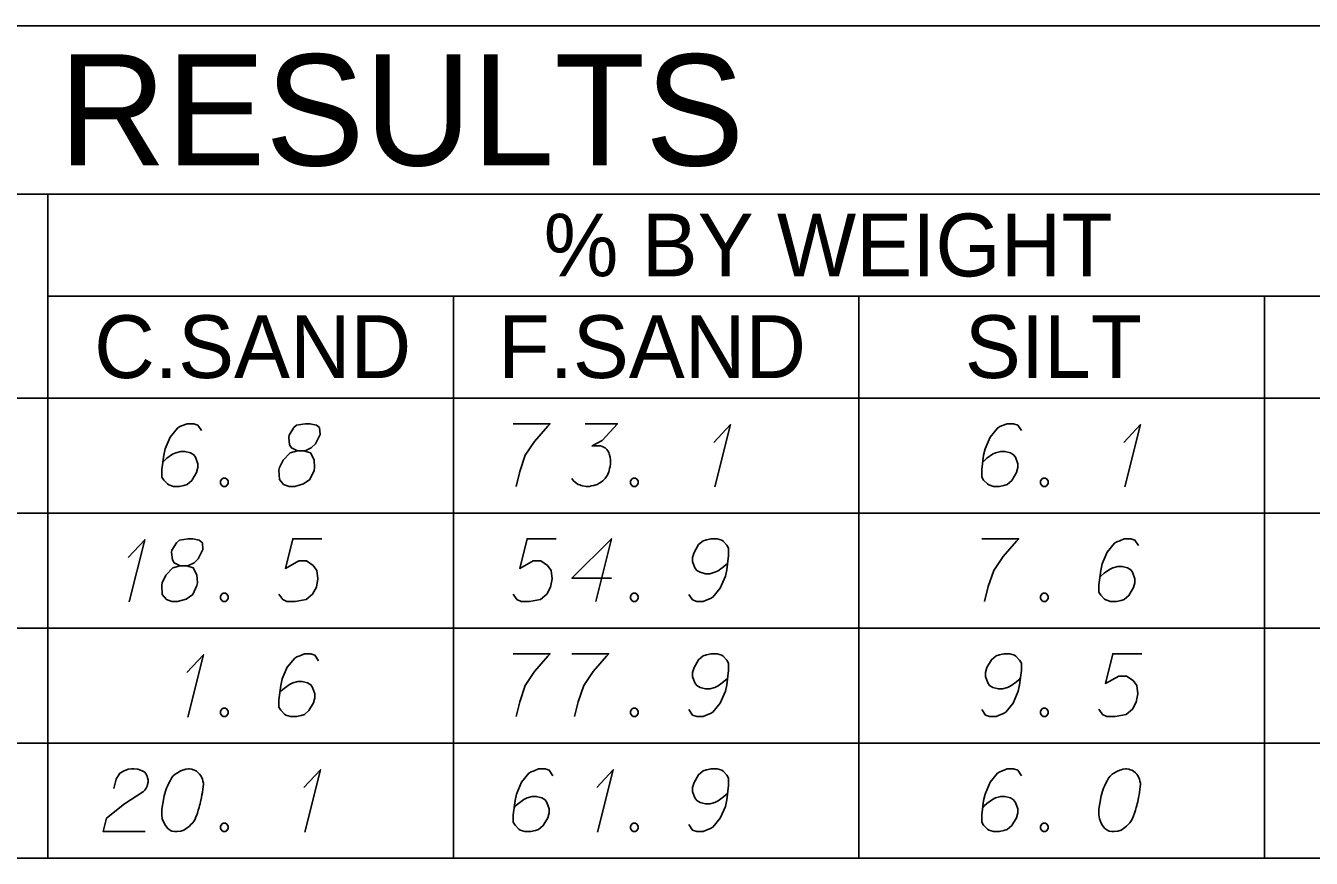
# Model space of a CAD drawing. Extents: x 2074207 to 2076812, y 516372 to 523312.
# Drawn here: x 2076524.4 to 2076622.7, y 516953.6 to 517017.2 of the extents above; entities that cross this region are included whole.
import ezdxf

# ---------------------------------------------------------------- set-up
doc = ezdxf.new("R2010")
doc.units = 0
for name, color, linetype in [('Prop DirtTable_ Soil Test Results - Outline (Major)', 7, 'Continuous'), ('Prop DirtTable_ Soil Test Results - Outline (Minor)', 7, 'Continuous'), ('Prop DirtTable_ Soil Test Results - Tx (Header - Large)', 7, 'Continuous'), ('Prop DirtTable_ Soil Test Results - Tx (Header - Small)', 7, 'Continuous'), ('Prop DirtTable_ Soil Test Results - Tx (Sample Data)', 7, 'Continuous')]:
    doc.layers.add(name, color=color, linetype=linetype)

msp = doc.modelspace()

# ---------------------------------------------------------------- linework, layer by layer
at = {"layer": 'Prop DirtTable_ Soil Test Results - Outline (Major)'}
for p, q in [((2076260.609, 517017.246), (2076811.903, 517017.246)), ((2076260.609, 516988.761), (2076811.903, 516988.761)), ((2076260.609, 516988.761), (2076811.903, 516988.761)), ((2076260.609, 516953.561), (2076811.903, 516953.561))]:
    msp.add_line(p, q, dxfattribs=at)
at = {"layer": 'Prop DirtTable_ Soil Test Results - Outline (Minor)'}
for p, q in [((2076260.609, 517004.361), (2076811.903, 517004.361)), ((2076526.074, 517004.361), (2076526.074, 516979.961)), ((2076526.074, 516996.561), (2076731.93, 516996.561)), ((2076557.094, 516996.561), (2076557.094, 516979.961)), ((2076588.114, 516996.561), (2076588.114, 516979.961)), ((2076619.134, 516979.961), (2076619.134, 516996.561)), ((2076260.609, 516979.961), (2076811.903, 516979.961)), ((2076260.609, 516979.961), (2076811.903, 516979.961)), ((2076526.074, 516979.961), (2076526.074, 516971.161)), ((2076557.094, 516979.961), (2076557.094, 516971.161)), ((2076588.114, 516979.961), (2076588.114, 516971.161)), ((2076619.134, 516971.161), (2076619.134, 516979.961)), ((2076260.609, 516971.161), (2076811.903, 516971.161)), ((2076260.609, 516971.161), (2076811.903, 516971.161)), ((2076526.074, 516971.161), (2076526.074, 516962.361)), ((2076557.094, 516971.161), (2076557.094, 516962.361)), ((2076588.114, 516971.161), (2076588.114, 516962.361)), ((2076619.134, 516962.361), (2076619.134, 516971.161)), ((2076260.609, 516962.361), (2076811.903, 516962.361)), ((2076260.609, 516962.361), (2076811.903, 516962.361)), ((2076526.074, 516962.361), (2076526.074, 516953.561)), ((2076557.094, 516962.361), (2076557.094, 516953.561)), ((2076588.114, 516962.361), (2076588.114, 516953.561)), ((2076619.134, 516953.561), (2076619.134, 516962.361)), ((2076260.609, 516953.561), (2076811.903, 516953.561))]:
    msp.add_line(p, q, dxfattribs=at)
at = {"layer": 'Prop DirtTable_ Soil Test Results - Tx (Sample Data)'}
for points in [[(2076537.829, 516986.276), (2076537.547, 516986.692), (2076537.23, 516986.805), (2076536.736, 516986.805), (2076536.383, 516986.654), (2076536.171, 516986.578), (2076535.995, 516986.465), (2076535.431, 516985.785), (2076535.043, 516984.878), (2076534.937, 516984.386), (2076534.796, 516983.29), (2076534.796, 516982.723), (2076534.937, 516982.496), (2076535.219, 516982.194), (2076535.325, 516982.119), (2076535.678, 516982.005), (2076536.136, 516982.005), (2076536.489, 516982.081), (2076536.736, 516982.156), (2076537.089, 516982.459), (2076537.441, 516983.063), (2076537.547, 516983.441), (2076537.547, 516983.744), (2076537.371, 516984.235), (2076537.23, 516984.424), (2076536.983, 516984.575), (2076536.559, 516984.689), (2076536.242, 516984.689), (2076535.854, 516984.575), (2076535.607, 516984.462), (2076535.184, 516984.159), (2076534.972, 516983.97), (2076534.866, 516983.857)], [(2076545.167, 516984.726), (2076545.66, 516984.726), (2076545.802, 516984.764), (2076546.225, 516984.953), (2076546.542, 516985.256), (2076546.895, 516985.974), (2076546.86, 516986.503), (2076546.613, 516986.692), (2076546.119, 516986.805), (2076545.766, 516986.805), (2076545.096, 516986.692), (2076544.884, 516986.503), (2076544.532, 516985.936), (2076544.496, 516985.747), (2076544.567, 516985.18), (2076544.708, 516984.953), (2076545.167, 516984.726), (2076544.602, 516984.575), (2076544.073, 516984.008), (2076543.791, 516983.441), (2076543.756, 516983.252), (2076543.791, 516982.534), (2076544.108, 516982.156), (2076544.532, 516982.005), (2076544.955, 516982.005), (2076545.625, 516982.194), (2076546.119, 516982.534), (2076546.437, 516983.215), (2076546.472, 516983.441), (2076546.437, 516984.046), (2076546.154, 516984.575), (2076545.66, 516984.726)], [(2076561.676, 516986.805), (2076564.498, 516986.805), (2076564.321, 516986.616), (2076563.298, 516985.444), (2076562.593, 516984.386), (2076562.169, 516983.139), (2076561.887, 516982.005)], [(2076567.179, 516986.805), (2076569.648, 516986.805), (2076568.484, 516985.52), (2076567.708, 516985.104), (2076568.343, 516985.104), (2076568.484, 516985.067), (2076568.554, 516985.029), (2076568.625, 516984.991), (2076568.695, 516984.953), (2076568.837, 516984.84), (2076568.907, 516984.726), (2076568.978, 516984.613), (2076569.013, 516984.5), (2076569.083, 516984.235), (2076569.119, 516984.008), (2076569.119, 516983.895), (2076569.119, 516983.744), (2076569.083, 516983.517), (2076569.048, 516983.366), (2076569.013, 516983.215), (2076568.978, 516983.101), (2076568.942, 516983.026), (2076568.907, 516982.95), (2076568.872, 516982.874), (2076568.801, 516982.761), (2076568.695, 516982.61), (2076568.59, 516982.496), (2076568.519, 516982.421), (2076568.413, 516982.345), (2076568.307, 516982.27), (2076568.166, 516982.194), (2076568.096, 516982.156), (2076567.849, 516982.081), (2076567.637, 516982.043), (2076567.496, 516982.005), (2076567.249, 516982.005), (2076566.967, 516982.043), (2076566.861, 516982.081), (2076566.755, 516982.119), (2076566.649, 516982.156), (2076566.544, 516982.232), (2076566.438, 516982.307), (2076566.261, 516982.459), (2076566.156, 516982.61)], [(2076577.02, 516985.369), (2076578.29, 516986.73), (2076577.091, 516981.967)], [(2076600.549, 516986.276), (2076600.267, 516986.692), (2076599.95, 516986.805), (2076599.456, 516986.805), (2076599.103, 516986.654), (2076598.891, 516986.578), (2076598.715, 516986.465), (2076598.151, 516985.785), (2076597.763, 516984.878), (2076597.657, 516984.386), (2076597.516, 516983.29), (2076597.516, 516982.723), (2076597.657, 516982.496), (2076597.939, 516982.194), (2076598.045, 516982.119), (2076598.398, 516982.005), (2076598.856, 516982.005), (2076599.209, 516982.081), (2076599.456, 516982.156), (2076599.809, 516982.459), (2076600.161, 516983.063), (2076600.267, 516983.441), (2076600.267, 516983.744), (2076600.091, 516984.235), (2076599.95, 516984.424), (2076599.703, 516984.575), (2076599.279, 516984.689), (2076598.962, 516984.689), (2076598.574, 516984.575), (2076598.327, 516984.462), (2076597.904, 516984.159), (2076597.692, 516983.97), (2076597.586, 516983.857)], [(2076608.38, 516985.369), (2076609.65, 516986.73), (2076608.451, 516981.967)], [(2076539.487, 516982.648), (2076539.664, 516982.648), (2076539.769, 516982.572), (2076539.875, 516982.421), (2076539.875, 516982.232), (2076539.769, 516982.081), (2076539.664, 516982.005), (2076539.487, 516982.005), (2076539.381, 516982.081), (2076539.276, 516982.232), (2076539.276, 516982.421), (2076539.381, 516982.572), (2076539.487, 516982.648)], [(2076570.847, 516982.648), (2076571.024, 516982.648), (2076571.129, 516982.572), (2076571.235, 516982.421), (2076571.235, 516982.232), (2076571.129, 516982.081), (2076571.024, 516982.005), (2076570.847, 516982.005), (2076570.741, 516982.081), (2076570.636, 516982.232), (2076570.636, 516982.421), (2076570.741, 516982.572), (2076570.847, 516982.648)], [(2076602.207, 516982.648), (2076602.384, 516982.648), (2076602.489, 516982.572), (2076602.595, 516982.421), (2076602.595, 516982.232), (2076602.489, 516982.081), (2076602.384, 516982.005), (2076602.207, 516982.005), (2076602.101, 516982.081), (2076601.996, 516982.232), (2076601.996, 516982.421), (2076602.101, 516982.572), (2076602.207, 516982.648)], [(2076532.22, 516976.569), (2076533.49, 516977.93), (2076532.291, 516973.167)], [(2076536.207, 516975.926), (2076536.7, 516975.926), (2076536.842, 516975.964), (2076537.265, 516976.153), (2076537.582, 516976.456), (2076537.935, 516977.174), (2076537.9, 516977.703), (2076537.653, 516977.892), (2076537.159, 516978.005), (2076536.806, 516978.005), (2076536.136, 516977.892), (2076535.924, 516977.703), (2076535.572, 516977.136), (2076535.536, 516976.947), (2076535.607, 516976.38), (2076535.748, 516976.153), (2076536.207, 516975.926), (2076535.642, 516975.775), (2076535.113, 516975.208), (2076534.831, 516974.641), (2076534.796, 516974.452), (2076534.831, 516973.734), (2076535.148, 516973.356), (2076535.572, 516973.205), (2076535.995, 516973.205), (2076536.665, 516973.394), (2076537.159, 516973.734), (2076537.477, 516974.415), (2076537.512, 516974.641), (2076537.477, 516975.246), (2076537.194, 516975.775), (2076536.7, 516975.926)], [(2076547.036, 516978.005), (2076544.814, 516978.005), (2076544.249, 516975.737), (2076545.272, 516976.304), (2076545.872, 516976.304), (2076546.366, 516975.964), (2076546.648, 516975.586), (2076546.719, 516974.944), (2076546.613, 516974.301), (2076546.331, 516973.772), (2076545.837, 516973.356), (2076544.99, 516973.205), (2076544.355, 516973.205), (2076544.038, 516973.356), (2076543.756, 516973.772)], [(2076564.956, 516978.005), (2076562.734, 516978.005), (2076562.169, 516975.737), (2076563.192, 516976.304), (2076563.792, 516976.304), (2076564.286, 516975.964), (2076564.568, 516975.586), (2076564.639, 516974.944), (2076564.533, 516974.301), (2076564.251, 516973.772), (2076563.757, 516973.356), (2076562.91, 516973.205), (2076562.275, 516973.205), (2076561.958, 516973.356), (2076561.676, 516973.772)], [(2076569.189, 516974.982), (2076566.156, 516974.982), (2076569.189, 516978.005), (2076567.99, 516973.205)], [(2076575.116, 516973.734), (2076575.398, 516973.319), (2076575.715, 516973.205), (2076576.209, 516973.205), (2076576.562, 516973.356), (2076576.774, 516973.432), (2076576.95, 516973.545), (2076577.514, 516974.226), (2076577.902, 516975.133), (2076578.008, 516975.624), (2076578.149, 516976.72), (2076578.149, 516977.287), (2076578.008, 516977.514), (2076577.726, 516977.816), (2076577.62, 516977.892), (2076577.267, 516978.005), (2076576.809, 516978.005), (2076576.456, 516977.93), (2076576.209, 516977.854), (2076575.856, 516977.552), (2076575.504, 516976.947), (2076575.398, 516976.569), (2076575.398, 516976.267), (2076575.574, 516975.775), (2076575.715, 516975.586), (2076575.962, 516975.435), (2076576.386, 516975.322), (2076576.703, 516975.322), (2076577.091, 516975.435), (2076577.338, 516975.548), (2076577.761, 516975.851), (2076577.973, 516976.04), (2076578.079, 516976.153)], [(2076597.516, 516978.005), (2076600.338, 516978.005), (2076600.161, 516977.816), (2076599.138, 516976.644), (2076598.433, 516975.586), (2076598.009, 516974.339), (2076597.727, 516973.205)], [(2076609.509, 516977.476), (2076609.227, 516977.892), (2076608.91, 516978.005), (2076608.416, 516978.005), (2076608.063, 516977.854), (2076607.851, 516977.778), (2076607.675, 516977.665), (2076607.111, 516976.985), (2076606.723, 516976.078), (2076606.617, 516975.586), (2076606.476, 516974.49), (2076606.476, 516973.923), (2076606.617, 516973.696), (2076606.899, 516973.394), (2076607.005, 516973.319), (2076607.358, 516973.205), (2076607.816, 516973.205), (2076608.169, 516973.281), (2076608.416, 516973.356), (2076608.769, 516973.659), (2076609.121, 516974.263), (2076609.227, 516974.641), (2076609.227, 516974.944), (2076609.051, 516975.435), (2076608.91, 516975.624), (2076608.663, 516975.775), (2076608.239, 516975.889), (2076607.922, 516975.889), (2076607.534, 516975.775), (2076607.287, 516975.662), (2076606.864, 516975.359), (2076606.652, 516975.17), (2076606.546, 516975.057)], [(2076539.487, 516973.848), (2076539.664, 516973.848), (2076539.769, 516973.772), (2076539.875, 516973.621), (2076539.875, 516973.432), (2076539.769, 516973.281), (2076539.664, 516973.205), (2076539.487, 516973.205), (2076539.381, 516973.281), (2076539.276, 516973.432), (2076539.276, 516973.621), (2076539.381, 516973.772), (2076539.487, 516973.848)], [(2076570.847, 516973.848), (2076571.024, 516973.848), (2076571.129, 516973.772), (2076571.235, 516973.621), (2076571.235, 516973.432), (2076571.129, 516973.281), (2076571.024, 516973.205), (2076570.847, 516973.205), (2076570.741, 516973.281), (2076570.636, 516973.432), (2076570.636, 516973.621), (2076570.741, 516973.772), (2076570.847, 516973.848)], [(2076602.207, 516973.848), (2076602.384, 516973.848), (2076602.489, 516973.772), (2076602.595, 516973.621), (2076602.595, 516973.432), (2076602.489, 516973.281), (2076602.384, 516973.205), (2076602.207, 516973.205), (2076602.101, 516973.281), (2076601.996, 516973.432), (2076601.996, 516973.621), (2076602.101, 516973.772), (2076602.207, 516973.848)], [(2076536.7, 516967.769), (2076537.97, 516969.13), (2076536.771, 516964.367)], [(2076546.789, 516968.676), (2076546.507, 516969.092), (2076546.19, 516969.205), (2076545.696, 516969.205), (2076545.343, 516969.054), (2076545.131, 516968.978), (2076544.955, 516968.865), (2076544.391, 516968.185), (2076544.003, 516967.278), (2076543.897, 516966.786), (2076543.756, 516965.69), (2076543.756, 516965.123), (2076543.897, 516964.896), (2076544.179, 516964.594), (2076544.285, 516964.519), (2076544.638, 516964.405), (2076545.096, 516964.405), (2076545.449, 516964.481), (2076545.696, 516964.556), (2076546.049, 516964.859), (2076546.401, 516965.463), (2076546.507, 516965.841), (2076546.507, 516966.144), (2076546.331, 516966.635), (2076546.19, 516966.824), (2076545.943, 516966.975), (2076545.519, 516967.089), (2076545.202, 516967.089), (2076544.814, 516966.975), (2076544.567, 516966.862), (2076544.144, 516966.559), (2076543.932, 516966.37), (2076543.826, 516966.257)], [(2076561.676, 516969.205), (2076564.498, 516969.205), (2076564.321, 516969.016), (2076563.298, 516967.844), (2076562.593, 516966.786), (2076562.169, 516965.539), (2076561.887, 516964.405)], [(2076566.156, 516969.205), (2076568.978, 516969.205), (2076568.801, 516969.016), (2076567.778, 516967.844), (2076567.073, 516966.786), (2076566.649, 516965.539), (2076566.367, 516964.405)], [(2076575.116, 516964.934), (2076575.398, 516964.519), (2076575.715, 516964.405), (2076576.209, 516964.405), (2076576.562, 516964.556), (2076576.774, 516964.632), (2076576.95, 516964.745), (2076577.514, 516965.426), (2076577.902, 516966.333), (2076578.008, 516966.824), (2076578.149, 516967.92), (2076578.149, 516968.487), (2076578.008, 516968.714), (2076577.726, 516969.016), (2076577.62, 516969.092), (2076577.267, 516969.205), (2076576.809, 516969.205), (2076576.456, 516969.13), (2076576.209, 516969.054), (2076575.856, 516968.752), (2076575.504, 516968.147), (2076575.398, 516967.769), (2076575.398, 516967.467), (2076575.574, 516966.975), (2076575.715, 516966.786), (2076575.962, 516966.635), (2076576.386, 516966.522), (2076576.703, 516966.522), (2076577.091, 516966.635), (2076577.338, 516966.748), (2076577.761, 516967.051), (2076577.973, 516967.24), (2076578.079, 516967.353)], [(2076597.516, 516964.934), (2076597.798, 516964.519), (2076598.115, 516964.405), (2076598.609, 516964.405), (2076598.962, 516964.556), (2076599.174, 516964.632), (2076599.35, 516964.745), (2076599.914, 516965.426), (2076600.302, 516966.333), (2076600.408, 516966.824), (2076600.549, 516967.92), (2076600.549, 516968.487), (2076600.408, 516968.714), (2076600.126, 516969.016), (2076600.02, 516969.092), (2076599.667, 516969.205), (2076599.209, 516969.205), (2076598.856, 516969.13), (2076598.609, 516969.054), (2076598.256, 516968.752), (2076597.904, 516968.147), (2076597.798, 516967.769), (2076597.798, 516967.467), (2076597.974, 516966.975), (2076598.115, 516966.786), (2076598.362, 516966.635), (2076598.786, 516966.522), (2076599.103, 516966.522), (2076599.491, 516966.635), (2076599.738, 516966.748), (2076600.161, 516967.051), (2076600.373, 516967.24), (2076600.479, 516967.353)], [(2076609.756, 516969.205), (2076607.534, 516969.205), (2076606.969, 516966.937), (2076607.992, 516967.504), (2076608.592, 516967.504), (2076609.086, 516967.164), (2076609.368, 516966.786), (2076609.439, 516966.144), (2076609.333, 516965.501), (2076609.051, 516964.972), (2076608.557, 516964.556), (2076607.71, 516964.405), (2076607.075, 516964.405), (2076606.758, 516964.556), (2076606.476, 516964.972)], [(2076539.487, 516965.048), (2076539.664, 516965.048), (2076539.769, 516964.972), (2076539.875, 516964.821), (2076539.875, 516964.632), (2076539.769, 516964.481), (2076539.664, 516964.405), (2076539.487, 516964.405), (2076539.381, 516964.481), (2076539.276, 516964.632), (2076539.276, 516964.821), (2076539.381, 516964.972), (2076539.487, 516965.048)], [(2076570.847, 516965.048), (2076571.024, 516965.048), (2076571.129, 516964.972), (2076571.235, 516964.821), (2076571.235, 516964.632), (2076571.129, 516964.481), (2076571.024, 516964.405), (2076570.847, 516964.405), (2076570.741, 516964.481), (2076570.636, 516964.632), (2076570.636, 516964.821), (2076570.741, 516964.972), (2076570.847, 516965.048)], [(2076602.207, 516965.048), (2076602.384, 516965.048), (2076602.489, 516964.972), (2076602.595, 516964.821), (2076602.595, 516964.632), (2076602.489, 516964.481), (2076602.384, 516964.405), (2076602.207, 516964.405), (2076602.101, 516964.481), (2076601.996, 516964.632), (2076601.996, 516964.821), (2076602.101, 516964.972), (2076602.207, 516965.048)], [(2076531.127, 516958.893), (2076531.303, 516959.611), (2076531.586, 516960.065), (2076531.903, 516960.254), (2076532.22, 516960.367), (2076532.467, 516960.405), (2076532.644, 516960.405), (2076532.961, 516960.367), (2076533.173, 516960.292), (2076533.279, 516960.254), (2076533.49, 516960.141), (2076533.596, 516959.989), (2076533.667, 516959.838), (2076533.702, 516959.725), (2076533.737, 516959.574), (2076533.737, 516959.385), (2076533.702, 516959.196), (2076533.667, 516959.082), (2076533.596, 516958.931), (2076533.49, 516958.78), (2076533.385, 516958.667), (2076531.938, 516957.722), (2076530.563, 516956.626), (2076530.316, 516955.605), (2076533.526, 516955.605)], [(2076536.912, 516960.405), (2076536.842, 516960.405), (2076536.63, 516960.367), (2076536.489, 516960.33), (2076536.383, 516960.292), (2076536.207, 516960.216), (2076535.995, 516960.103), (2076535.819, 516959.989), (2076535.642, 516959.838), (2076535.536, 516959.687), (2076535.431, 516959.498), (2076535.325, 516959.309), (2076535.219, 516959.082), (2076535.148, 516958.931), (2076535.078, 516958.704), (2076534.972, 516958.326), (2076534.866, 516957.759), (2076534.796, 516957.306), (2076534.796, 516956.89), (2076534.831, 516956.588), (2076534.972, 516956.248), (2076535.078, 516956.059), (2076535.254, 516955.832), (2076535.466, 516955.681), (2076535.572, 516955.643), (2076535.783, 516955.605), (2076535.96, 516955.605), (2076536.242, 516955.643), (2076536.489, 516955.719), (2076536.665, 516955.832), (2076536.912, 516956.021), (2076537.018, 516956.134), (2076537.159, 516956.285), (2076537.265, 516956.437), (2076537.335, 516956.55), (2076537.406, 516956.739), (2076537.441, 516956.815), (2076537.512, 516957.004), (2076537.582, 516957.23), (2076537.653, 516957.457), (2076537.688, 516957.608), (2076537.723, 516957.722), (2076537.759, 516957.873), (2076537.829, 516958.213), (2076537.865, 516958.402), (2076537.9, 516958.591), (2076537.935, 516958.856), (2076537.97, 516959.196), (2076537.97, 516959.309), (2076537.935, 516959.46), (2076537.9, 516959.611), (2076537.794, 516959.838), (2076537.688, 516959.989), (2076537.582, 516960.103), (2076537.441, 516960.216), (2076537.3, 516960.292), (2076537.194, 516960.33), (2076537.089, 516960.367), (2076536.912, 516960.405)], [(2076545.66, 516958.969), (2076546.93, 516960.33), (2076545.731, 516955.567)], [(2076564.709, 516959.876), (2076564.427, 516960.292), (2076564.11, 516960.405), (2076563.616, 516960.405), (2076563.263, 516960.254), (2076563.051, 516960.178), (2076562.875, 516960.065), (2076562.311, 516959.385), (2076561.923, 516958.478), (2076561.817, 516957.986), (2076561.676, 516956.89), (2076561.676, 516956.323), (2076561.817, 516956.096), (2076562.099, 516955.794), (2076562.205, 516955.719), (2076562.558, 516955.605), (2076563.016, 516955.605), (2076563.369, 516955.681), (2076563.616, 516955.756), (2076563.969, 516956.059), (2076564.321, 516956.663), (2076564.427, 516957.041), (2076564.427, 516957.344), (2076564.251, 516957.835), (2076564.11, 516958.024), (2076563.863, 516958.175), (2076563.439, 516958.289), (2076563.122, 516958.289), (2076562.734, 516958.175), (2076562.487, 516958.062), (2076562.064, 516957.759), (2076561.852, 516957.57), (2076561.746, 516957.457)], [(2076568.06, 516958.969), (2076569.33, 516960.33), (2076568.131, 516955.567)], [(2076575.116, 516956.134), (2076575.398, 516955.719), (2076575.715, 516955.605), (2076576.209, 516955.605), (2076576.562, 516955.756), (2076576.774, 516955.832), (2076576.95, 516955.945), (2076577.514, 516956.626), (2076577.902, 516957.533), (2076578.008, 516958.024), (2076578.149, 516959.12), (2076578.149, 516959.687), (2076578.008, 516959.914), (2076577.726, 516960.216), (2076577.62, 516960.292), (2076577.267, 516960.405), (2076576.809, 516960.405), (2076576.456, 516960.33), (2076576.209, 516960.254), (2076575.856, 516959.952), (2076575.504, 516959.347), (2076575.398, 516958.969), (2076575.398, 516958.667), (2076575.574, 516958.175), (2076575.715, 516957.986), (2076575.962, 516957.835), (2076576.386, 516957.722), (2076576.703, 516957.722), (2076577.091, 516957.835), (2076577.338, 516957.948), (2076577.761, 516958.251), (2076577.973, 516958.44), (2076578.079, 516958.553)], [(2076600.549, 516959.876), (2076600.267, 516960.292), (2076599.95, 516960.405), (2076599.456, 516960.405), (2076599.103, 516960.254), (2076598.891, 516960.178), (2076598.715, 516960.065), (2076598.151, 516959.385), (2076597.763, 516958.478), (2076597.657, 516957.986), (2076597.516, 516956.89), (2076597.516, 516956.323), (2076597.657, 516956.096), (2076597.939, 516955.794), (2076598.045, 516955.719), (2076598.398, 516955.605), (2076598.856, 516955.605), (2076599.209, 516955.681), (2076599.456, 516955.756), (2076599.809, 516956.059), (2076600.161, 516956.663), (2076600.267, 516957.041), (2076600.267, 516957.344), (2076600.091, 516957.835), (2076599.95, 516958.024), (2076599.703, 516958.175), (2076599.279, 516958.289), (2076598.962, 516958.289), (2076598.574, 516958.175), (2076598.327, 516958.062), (2076597.904, 516957.759), (2076597.692, 516957.57), (2076597.586, 516957.457)], [(2076608.592, 516960.405), (2076608.522, 516960.405), (2076608.31, 516960.367), (2076608.169, 516960.33), (2076608.063, 516960.292), (2076607.887, 516960.216), (2076607.675, 516960.103), (2076607.499, 516959.989), (2076607.322, 516959.838), (2076607.216, 516959.687), (2076607.111, 516959.498), (2076607.005, 516959.309), (2076606.899, 516959.082), (2076606.828, 516958.931), (2076606.758, 516958.704), (2076606.652, 516958.326), (2076606.546, 516957.759), (2076606.476, 516957.306), (2076606.476, 516956.89), (2076606.511, 516956.588), (2076606.652, 516956.248), (2076606.758, 516956.059), (2076606.934, 516955.832), (2076607.146, 516955.681), (2076607.252, 516955.643), (2076607.463, 516955.605), (2076607.64, 516955.605), (2076607.922, 516955.643), (2076608.169, 516955.719), (2076608.345, 516955.832), (2076608.592, 516956.021), (2076608.698, 516956.134), (2076608.839, 516956.285), (2076608.945, 516956.437), (2076609.015, 516956.55), (2076609.086, 516956.739), (2076609.121, 516956.815), (2076609.192, 516957.004), (2076609.262, 516957.23), (2076609.333, 516957.457), (2076609.368, 516957.608), (2076609.403, 516957.722), (2076609.439, 516957.873), (2076609.509, 516958.213), (2076609.545, 516958.402), (2076609.58, 516958.591), (2076609.615, 516958.856), (2076609.65, 516959.196), (2076609.65, 516959.309), (2076609.615, 516959.46), (2076609.58, 516959.611), (2076609.474, 516959.838), (2076609.368, 516959.989), (2076609.262, 516960.103), (2076609.121, 516960.216), (2076608.98, 516960.292), (2076608.874, 516960.33), (2076608.769, 516960.367), (2076608.592, 516960.405)], [(2076539.487, 516956.248), (2076539.664, 516956.248), (2076539.769, 516956.172), (2076539.875, 516956.021), (2076539.875, 516955.832), (2076539.769, 516955.681), (2076539.664, 516955.605), (2076539.487, 516955.605), (2076539.381, 516955.681), (2076539.276, 516955.832), (2076539.276, 516956.021), (2076539.381, 516956.172), (2076539.487, 516956.248)], [(2076570.847, 516956.248), (2076571.024, 516956.248), (2076571.129, 516956.172), (2076571.235, 516956.021), (2076571.235, 516955.832), (2076571.129, 516955.681), (2076571.024, 516955.605), (2076570.847, 516955.605), (2076570.741, 516955.681), (2076570.636, 516955.832), (2076570.636, 516956.021), (2076570.741, 516956.172), (2076570.847, 516956.248)], [(2076602.207, 516956.248), (2076602.384, 516956.248), (2076602.489, 516956.172), (2076602.595, 516956.021), (2076602.595, 516955.832), (2076602.489, 516955.681), (2076602.384, 516955.605), (2076602.207, 516955.605), (2076602.101, 516955.681), (2076601.996, 516955.832), (2076601.996, 516956.021), (2076602.101, 516956.172), (2076602.207, 516956.248)]]:
    msp.add_lwpolyline(points, dxfattribs=at)

# ---------------------------------------------------------------- texts
at = {"layer": 'Prop DirtTable_ Soil Test Results - Tx (Header - Large)'}
msp.add_text('SOIL TEST RESULTS', height=8.50001, dxfattribs=at).set_placement((2076465.656, 517006.554))
at = {"layer": 'Prop DirtTable_ Soil Test Results - Tx (Header - Small)'}
for s, height, p in [('% BY WEIGHT', 4.79998, (2076564.009, 516998.071)), ('C.SAND', 4.8, (2076529.618, 516990.296)), ('F.SAND', 4.8, (2076560.529, 516990.296)), ('SILT', 4.8, (2076596.215, 516990.296))]:
    msp.add_text(s, height=height, dxfattribs=at).set_placement(p)

doc.saveas('drawing.dxf')
